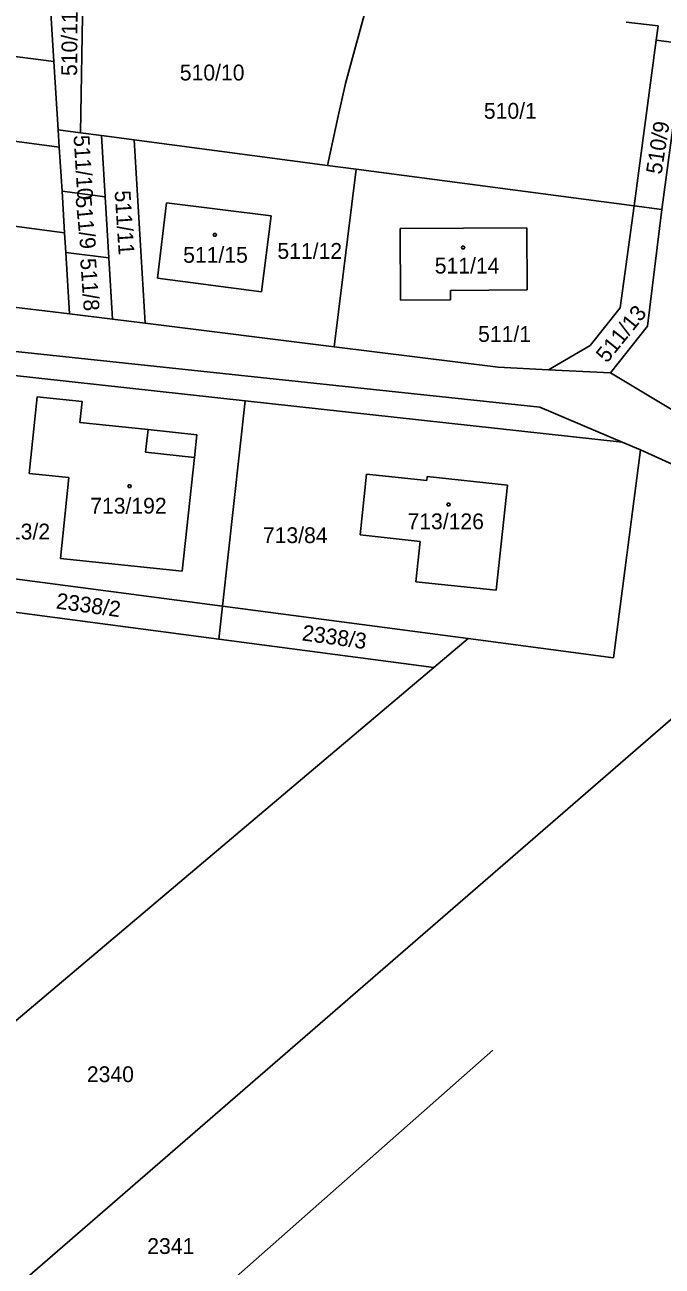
# Model space of a CAD drawing. Extents: x -639590 to -639298, y -1193269 to -1192863.
# Drawn here: x -639464.3 to -639395.8, y -1193117.1 to -1192983.6 of the extents above; entities that cross this region are included whole.
import ezdxf

# ---------------------------------------------------------------- set-up
doc = ezdxf.new("R2010")
doc.units = 0
for name, color, linetype in [('Vrstva 1', 7, 'Continuous'), ('Vrstva 2', 7, 'Continuous'), ('Vrstva 4', 7, 'Continuous'), ('Vrstva 5', 7, 'Continuous')]:
    doc.layers.add(name, color=color, linetype=linetype)

msp = doc.modelspace()

# ---------------------------------------------------------------- linework, layer by layer
at = {"layer": 'Vrstva 1'}
for p, q in [((-639461.13, -1192987.55), (-639461.73, -1192978.35)), ((-639458.02, -1192980.06), (-639458.26, -1192995.21)), ((-639427.17, -1192980.28), (-639429.8, -1192989.92)), ((-639399.63, -1192983.32), (-639396.19, -1192983.7)), ((-639396.19, -1192983.7), (-639396.4, -1192985.25)), ((-639483.9, -1192984.59), (-639461.13, -1192987.55)), ((-639396.4, -1192985.25), (-639398.77, -1193003.07)), ((-639396.4, -1192985.25), (-639393.41, -1192985.63)), ((-639393.41, -1192985.63), (-639395.79, -1193003.46)), ((-639460.66, -1192994.89), (-639461.13, -1192987.55)), ((-639429.8, -1192989.92), (-639430.58, -1192993.42)), ((-639430.58, -1192993.42), (-639431.72, -1192998.71)), ((-639460.55, -1192996.75), (-639483.21, -1192993.78)), ((-639458.26, -1192995.21), (-639460.66, -1192994.89)), ((-639460.55, -1192996.75), (-639460.66, -1192994.89)), ((-639456.03, -1192995.5), (-639458.26, -1192995.21)), ((-639456.03, -1192995.5), (-639455.63, -1193002.09)), ((-639452.5, -1192995.97), (-639456.03, -1192995.5)), ((-639431.72, -1192998.71), (-639452.5, -1192995.97)), ((-639452.5, -1192995.97), (-639451.31, -1193015.69)), ((-639460.26, -1193001.5), (-639460.55, -1192996.75)), ((-639428.65, -1192999.12), (-639431.72, -1192998.71)), ((-639428.65, -1192999.12), (-639431.01, -1193018.22)), ((-639398.77, -1193003.07), (-639428.65, -1192999.12)), ((-639455.63, -1193002.09), (-639460.26, -1193001.5)), ((-639459.99, -1193005.96), (-639460.26, -1193001.5)), ((-639455.63, -1193002.09), (-639455.23, -1193008.67)), ((-639449.98, -1193010.83), (-639449.03, -1193002.74)), ((-639449.03, -1193002.74), (-639437.79, -1193004.15)), ((-639482.56, -1193002.99), (-639459.99, -1193005.96)), ((-639437.79, -1193004.15), (-639438.81, -1193012.29)), ((-639398.77, -1193003.07), (-639400.28, -1193014.04)), ((-639395.79, -1193003.46), (-639398.77, -1193003.07)), ((-639395.79, -1193003.46), (-639397.35, -1193015.99)), ((-639423.92, -1193005.5), (-639410.3, -1193005.42)), ((-639423.88, -1193013.19), (-639423.92, -1193005.5)), ((-639410.3, -1193005.42), (-639410.26, -1193012.08)), ((-639459.86, -1193008.08), (-639459.99, -1193005.96)), ((-639459.46, -1193014.67), (-639459.86, -1193008.08)), ((-639455.23, -1193008.67), (-639459.86, -1193008.08)), ((-639455.23, -1193008.67), (-639454.83, -1193015.25)), ((-639438.81, -1193012.29), (-639449.98, -1193010.83)), ((-639483.54, -1193011.82), (-639459.46, -1193014.67)), ((-639410.26, -1193012.08), (-639418.51, -1193012.16)), ((-639418.51, -1193012.16), (-639418.5, -1193013.15)), ((-639418.5, -1193013.15), (-639423.88, -1193013.19)), ((-639501.94, -1193014.81), (-639408.9, -1193024.71)), ((-639454.83, -1193015.25), (-639459.46, -1193014.67)), ((-639400.28, -1193014.04), (-639403.51, -1193018.07)), ((-639451.31, -1193015.69), (-639454.83, -1193015.25)), ((-639431.01, -1193018.22), (-639451.31, -1193015.69)), ((-639397.35, -1193015.99), (-639401.32, -1193021.01)), ((-639413.38, -1193020.42), (-639431.01, -1193018.22)), ((-639403.51, -1193018.07), (-639407.99, -1193020.68)), ((-639440.59, -1193024.01), (-639465.69, -1193021.25)), ((-639407.99, -1193020.68), (-639413.38, -1193020.42)), ((-639401.32, -1193021.01), (-639407.99, -1193020.68)), ((-639391.81, -1193026.72), (-639401.32, -1193021.01)), ((-639463.78, -1193031.84), (-639462.92, -1193023.59)), ((-639462.92, -1193023.59), (-639458.1, -1193024.1)), ((-639458.1, -1193024.1), (-639458.33, -1193026.34)), ((-639443.02, -1193046.1), (-639440.59, -1193024.01)), ((-639400.07, -1193028.47), (-639440.59, -1193024.01)), ((-639408.9, -1193024.71), (-639400.07, -1193028.47)), ((-639458.33, -1193026.34), (-639451.01, -1193027.12)), ((-639451.01, -1193027.12), (-639445.77, -1193027.68)), ((-639445.77, -1193027.68), (-639446.03, -1193030.1)), ((-639401, -1193051.65), (-639398.1, -1193029.3)), ((-639400.07, -1193028.47), (-639398.1, -1193029.3)), ((-639394.21, -1193031.06), (-639398.1, -1193029.3)), ((-639446.03, -1193030.1), (-639447.34, -1193042.34)), ((-639459.53, -1193032.26), (-639463.78, -1193031.84)), ((-639428.2, -1193038.43), (-639427.54, -1193031.91)), ((-639427.54, -1193031.91), (-639421.06, -1193032.6)), ((-639421.06, -1193032.6), (-639421.02, -1193032.17)), ((-639421.02, -1193032.17), (-639412.39, -1193033.08)), ((-639460.42, -1193040.96), (-639459.53, -1193032.26)), ((-639412.39, -1193033.08), (-639413.59, -1193044.39)), ((-639421.77, -1193039.15), (-639428.2, -1193038.43)), ((-639422.23, -1193043.48), (-639421.77, -1193039.15)), ((-639447.34, -1193042.34), (-639460.42, -1193040.96)), ((-639443.02, -1193046.1), (-639468.21, -1193042.77)), ((-639377.41, -1193043.16), (-639466.59, -1193120.49)), ((-639413.59, -1193044.39), (-639422.23, -1193043.48)), ((-639468.63, -1193046.32), (-639443.41, -1193049.65)), ((-639443.41, -1193049.65), (-639443.02, -1193046.1)), ((-639443.02, -1193046.1), (-639440.82, -1193046.39)), ((-639440.82, -1193046.39), (-639416.6, -1193049.59)), ((-639420.3, -1193052.71), (-639416.6, -1193049.59)), ((-639416.6, -1193049.59), (-639401, -1193051.65)), ((-639443.41, -1193049.65), (-639420.3, -1193052.71)), ((-639474.06, -1193098.11), (-639420.3, -1193052.71)), ((-639413.94, -1193093.82), (-639461.48, -1193135.8))]:
    msp.add_line(p, q, dxfattribs=at)
at = {"layer": 'Vrstva 4'}
for p, q in [((-639451.01, -1193027.12), (-639451.27, -1193029.54)), ((-639451.27, -1193029.54), (-639446.03, -1193030.1))]:
    msp.add_line(p, q, dxfattribs=at)
at = {"layer": 'Vrstva 5'}
for points in [[(-639443.73, -1193006.03), (-639443.64, -1193006.18), (-639443.73, -1193006.33), (-639443.91, -1193006.33), (-639444, -1193006.18), (-639443.91, -1193006.03)], [(-639417.07, -1193007.4), (-639416.98, -1193007.55), (-639417.07, -1193007.7), (-639417.25, -1193007.7), (-639417.34, -1193007.55), (-639417.25, -1193007.4)], [(-639452.9, -1193033.05), (-639452.81, -1193033.2), (-639452.9, -1193033.35), (-639453.08, -1193033.35), (-639453.17, -1193033.2), (-639453.08, -1193033.05)], [(-639418.62, -1193035.02), (-639418.53, -1193035.17), (-639418.62, -1193035.32), (-639418.8, -1193035.32), (-639418.89, -1193035.17), (-639418.8, -1193035.02)]]:
    msp.add_lwpolyline(points, close=True, dxfattribs=at)

# ---------------------------------------------------------------- texts
at = {"layer": 'Vrstva 2'}
for s, rotation, p in [('510/11', 89.5533, (-639458.64, -1192989.11)), ('510/9', 81.1308, (-639395.83, -1192999.74)), ('511/10', 273.4728, (-639459.02, -1192995.5)), ('511/11', 273.7019, (-639454.61, -1193001.46)), ('511/9', 275.3062, (-639458.81, -1193002.11)), ('511/8', 273.9884, (-639458.31, -1193008.75)), ('511/13', 51.0505, (-639401.7, -1193020.04)), ('2338/2', 352.1399, (-639460.97, -1193046.34)), ('2338/3', 352.1399, (-639434.54, -1193049.77))]:
    msp.add_text(s, height=1.7, rotation=rotation, dxfattribs=at).set_placement(p)
for s, p in [('510/10', (-639447.6, -1192989.58)), ('510/1', (-639414.92, -1192993.7)), ('511/15', (-639447.24, -1193009.18)), ('511/12', (-639437.11, -1193008.76)), ('511/14', (-639420.2, -1193010.34)), ('511/1', (-639415.54, -1193017.69)), ('713/192', (-639457.23, -1193036.15)), ('713/126', (-639423.13, -1193037.83)), ('713/2', (-639467.23, -1193038.93)), ('713/84', (-639438.67, -1193039.32)), ('2340', (-639457.59, -1193097.27)), ('2341', (-639451.1, -1193115.74))]:
    msp.add_text(s, height=1.7, dxfattribs=at).set_placement(p)

doc.saveas('drawing.dxf')
